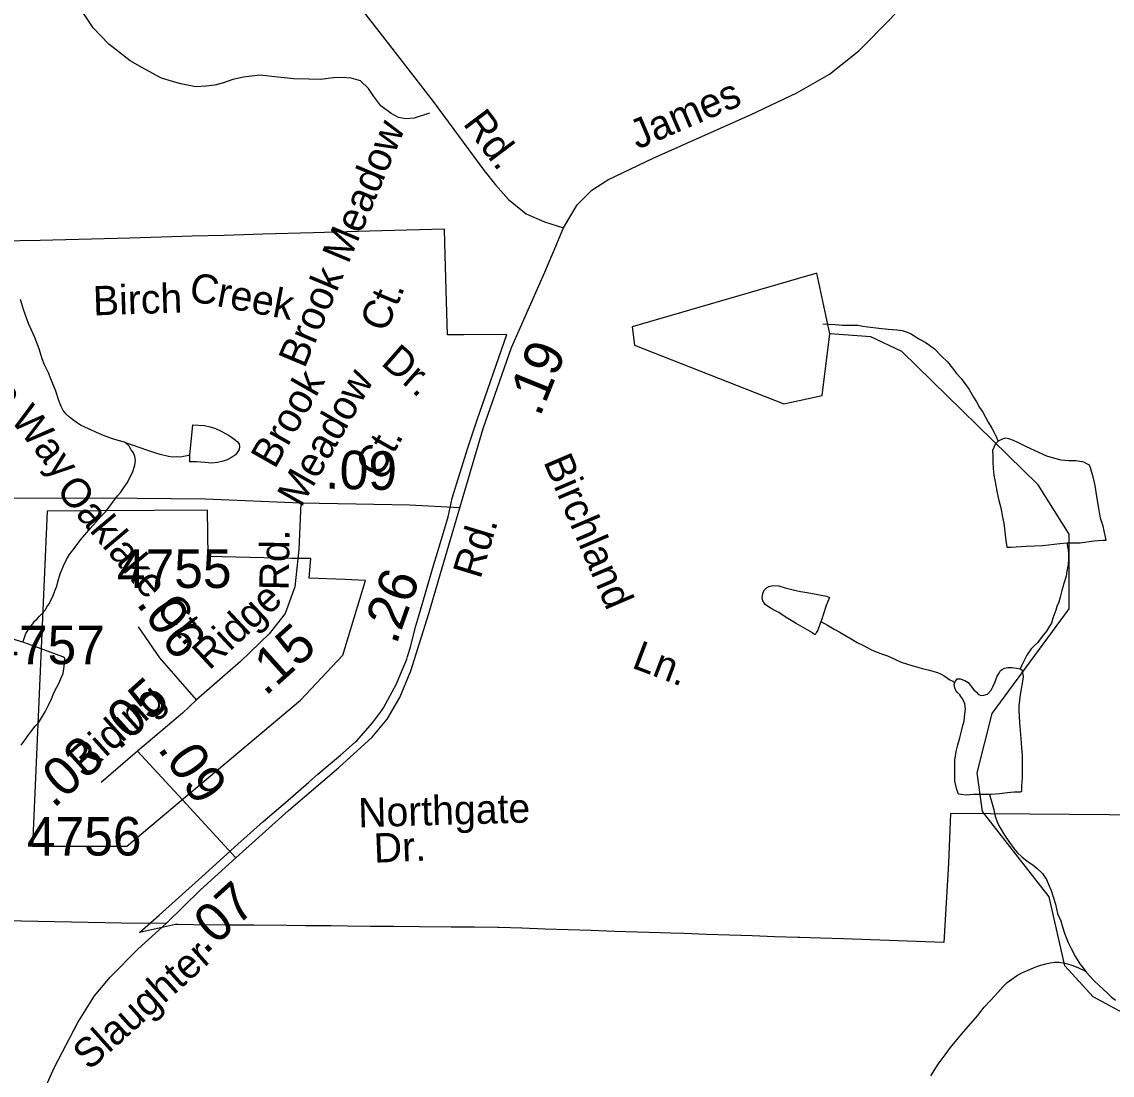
# Model space of a CAD drawing. Extents: x 2001466 to 2224147, y 644118 to 847247.
# Drawn here: x 2058752 to 2062288, y 676786 to 680203 of the extents above; entities that cross this region are included whole.
import ezdxf

# ---------------------------------------------------------------- set-up
doc = ezdxf.new("R2010")
doc.units = 0
for name, color, linetype in [('Exist Boundary Political City Limit New', 7, 'Continuous'), ('Exist Hydrographic Creek Single Shore', 7, 'Continuous'), ('Exist Hydrographic Misc Water Feature', 7, 'Continuous'), ('Exist Road Non-System Type 51', 7, 'Continuous'), ('Exist Road Non-System Type 51 Label', 7, 'Continuous'), ('Exist Road Secondary Mileage Hundredths English Label', 7, 'Continuous'), ('Exist Road Secondary Type 51 Attributed', 7, 'Continuous'), ('Exist Road Secondary Type 51 Label', 7, 'Continuous'), ('Exist Road Secondary Type 51 Number Label', 7, 'Continuous'), ('Map Preparation Boundary City Limit Buffer Line', 7, 'Continuous')]:
    doc.layers.add(name, color=color, linetype=linetype)

msp = doc.modelspace()

# ---------------------------------------------------------------- linework, layer by layer
at = {"layer": 'Exist Boundary Political City Limit New'}
for points in [[(2059452.1, 677535.1), (2059533.4, 677608.2), (2059607, 677670.7), (2059682.5, 677736.1), (2059712.1, 677762.4), (2059759.4, 677802.6), (2059785, 677824.4), (2059832.6, 677866.1), (2059838.1, 677870.9), (2059889.2, 677928.5), (2059918.5, 677968.4), (2059925, 677977.2), (2059966.5, 678055), (2059979.6, 678086.7), (2060000, 678135.8), (2060003, 678144), (2060012.4, 678174.8), (2060013.6, 678179.8), (2060029.4, 678243.4), (2060039.1, 678276.2), (2060067.4, 678372.6), (2060088.9, 678446.4), (2060096.4, 678471.2), (2060134.5, 678597.1), (2060147.6, 678657.4), (2060198.5, 678821.2), (2060227.9, 678911.3), (2060324.4, 679189.1), (2060185.2, 679187.9), (2060132.6, 679187.4), (2060130.5, 679258.9), (2060124.9, 679446), (2060122.4, 679530.6), (2060000, 679527), (2059879.4, 679523.6), (2059696.1, 679518.4), (2059533.2, 679513.8), (2059408, 679510.2), (2059303.9, 679507.2), (2059205, 679504.4), (2059102.2, 679501.5), (2058811.8, 679493.2), (2058678, 679491.1)], [(2059683.2, 678398.4), (2059688.8, 678462.5), (2059626.6, 678461.9), (2059356.6, 678468.5), (2059353.5, 678619.2), (2058834, 678615.1), (2058786.9, 677529.5), (2059092.8, 677529.5), (2059655.1, 678002.2), (2059792.6, 678148.9), (2059865.9, 678391.2), (2059798.8, 678393.9), (2059683.2, 678398.4)], [(2062406.8, 677630), (2061762.8, 677635.2), (2061756.4, 677473.4), (2061741.4, 677216.8), (2061504.9, 677225.1), (2061415.9, 677228.1), (2061341.9, 677230.6), (2061274.2, 677232.8), (2061268, 677233), (2061194, 677235.4), (2061120, 677237.9), (2061046.1, 677240.3), (2060972.1, 677242.8), (2060898.1, 677245.2), (2060854.9, 677246.6), (2060823.2, 677247.7), (2060748.2, 677250.2), (2060673.2, 677252.6), (2060598.4, 677255.1), (2060523.4, 677257.6), (2060448.4, 677260.1), (2060373.5, 677262.6), (2060298.5, 677265.1), (2060294.2, 677265.1), (2060219.5, 677265.8), (2060156.2, 677266.4), (2060144.5, 677266.5), (2060041.6, 677267.5), (2059957.6, 677268.2), (2059882.8, 677268.9), (2059807.8, 677269.7), (2059754.8, 677270.1), (2059671.8, 677270.9), (2059610.9, 677271.5), (2059503.9, 677272.3), (2059421.9, 677273.1), (2059309.8, 677274.1), (2059258.1, 677274.6), (2059250.2, 677274.9), (2059133.2, 677249.2)], [(2059133.2, 677249.2), (2059197.4, 677304.9), (2059335.2, 677429.4), (2059405.9, 677493.2), (2059452.1, 677535.1)]]:
    msp.add_lwpolyline(points, dxfattribs=at)
at = {"layer": 'Exist Hydrographic Creek Single Shore'}
msp.add_lwpolyline([(2062432.6, 676929.3), (2062225.6, 677040.6), (2062133.5, 677140.8), (2062083.5, 677365), (2061866.6, 677641.7), (2061849.6, 677766.6), (2061898.6, 677959.2), (2062148.5, 678298.7), (2062147.5, 678541.4), (2062047.6, 678701), (2061605.5, 679133.2), (2061504.7, 679181.1), (2061371.6, 679190.4)], dxfattribs=at)
at = {"layer": 'Exist Hydrographic Misc Water Feature'}
for points in [[(2061371.6, 679190.4), (2061329.5, 679388.1), (2060730.6, 679213.3), (2060738.6, 679154.1), (2061222.7, 678963.8), (2061347.6, 678990.8), (2061371.6, 679190.4)], [(2059088.1, 678836.8), (2059084.4, 678839.1), (2059064.5, 678844.9), (2059042.2, 678851.1), (2059016.6, 678860.7), (2058994.4, 678870.9), (2058976.2, 678879), (2058957.9, 678886.6), (2058942.3, 678894.6), (2058928.2, 678904.5), (2058916.1, 678912.8), (2058906.2, 678920.4), (2058896, 678930.5), (2058886.1, 678942.5), (2058880, 678954.8), (2058871.8, 678974.7), (2058861.9, 679004.5), (2058846.2, 679044.3), (2058838, 679064.6), (2058825.6, 679090.4), (2058818.1, 679110.2), (2058807.6, 679142.6), (2058793.7, 679178.4), (2058783.6, 679202.2), (2058773.8, 679224.4), (2058757.6, 679270.2), (2058747.5, 679302.2)], [(2061349.2, 679222.9), (2061389.2, 679221.3), (2061413.2, 679219.3), (2061429.4, 679219.3), (2061447.2, 679219.4), (2061463, 679219.4), (2061478.8, 679215.4), (2061495, 679213.4), (2061531.1, 679209.5), (2061560.8, 679205.4), (2061589.1, 679203.6), (2061607, 679201.7), (2061619.1, 679197.4), (2061633, 679191.7)], [(2061633, 679191.7), (2061663.2, 679173.7), (2061681, 679163.7), (2061695.1, 679153.8), (2061710.9, 679141.7), (2061733.3, 679119.7), (2061753.4, 679100), (2061769.2, 679079.8), (2061783.1, 679061.8), (2061797.5, 679045.9), (2061809.2, 679029.9), (2061823.3, 679009.9), (2061837.7, 678985.8), (2061847.7, 678970.1), (2061857.5, 678952), (2061867.6, 678936.3), (2061885.6, 678904.3), (2061897.5, 678884.3), (2061909.6, 678862.1), (2061917.8, 678842.2)], [(2059296.2, 678797.2), (2059306.3, 678895.5), (2059344.2, 678893.4), (2059362.3, 678889.4), (2059379.9, 678883.5), (2059398.2, 678875.4), (2059422.1, 678861.6), (2059432.2, 678855.7), (2059440.2, 678849.6), (2059449.8, 678841.6), (2059456.2, 678833.8), (2059457.8, 678825.8), (2059456.2, 678815.5), (2059450.2, 678805.9), (2059444.3, 678797.9), (2059432.2, 678789.6), (2059418.2, 678781.6), (2059404.3, 678777.6), (2059386.3, 678773.4), (2059368, 678771.7), (2059346.3, 678773.4), (2059318.2, 678775.6), (2059296.4, 678775.2), (2059296.2, 678797.2)], [(2062140.5, 678512.8), (2062184.2, 678512.7), (2062228.1, 678519), (2062257.8, 678521), (2062268.1, 678521), (2062257.8, 678566.8), (2062249.8, 678592.8), (2062243.7, 678624.9), (2062238.1, 678662.7), (2062231.8, 678698.9), (2062225.8, 678726.6), (2062221.7, 678740.6), (2062217.6, 678756.6), (2062213.9, 678764.9), (2062205.5, 678768.6), (2062195.5, 678774.6), (2062169.4, 678778.6), (2062145.6, 678778.5), (2062121.7, 678780.5), (2062101.8, 678786.4), (2062075.5, 678794.4), (2062035.7, 678812.6), (2062009.5, 678824.3), (2061981.8, 678838.3), (2061967.9, 678844.4), (2061951.9, 678850.1), (2061941.6, 678852.5), (2061933.6, 678850.4), (2061917.8, 678842.2)], [(2058755.5, 678190.4), (2058759.2, 678202.4), (2058765.4, 678218.6), (2058775.2, 678234.5), (2058781.4, 678242.5), (2058787.3, 678250.5), (2058793.2, 678258.5), (2058801.5, 678266.6), (2058809.2, 678274.8), (2058817.2, 678282.5), (2058827.5, 678294.8), (2058835.3, 678308.5), (2058841.2, 678316.6), (2058845.1, 678324.5), (2058852.9, 678338.7), (2058859.1, 678356.9), (2058865, 678372.6), (2058869.1, 678386.6), (2058876.7, 678412.6), (2058887.2, 678438.6), (2058896.8, 678458.6), (2058906.6, 678474.6), (2058924.7, 678498.6), (2058942.7, 678522.6), (2058956.5, 678538.8), (2058974.5, 678560.8), (2058992.8, 678580.8), (2059006.5, 678596.9), (2059024.3, 678614.9), (2059036.4, 678630.9), (2059046.9, 678644.8), (2059062.5, 678665.1), (2059072.5, 678677), (2059080.5, 678689.1), (2059094.5, 678708.9), (2059104.3, 678729), (2059110.5, 678741), (2059118.3, 678764.9), (2059120.1, 678780.9), (2059118.3, 678792.9), (2059114.4, 678804.9), (2059106.2, 678815), (2059100.2, 678826.9), (2059088.1, 678836.8)], [(2059296.2, 678797.2), (2059288.2, 678795.1), (2059276.1, 678793.3), (2059266.3, 678791.2), (2059254, 678791.4), (2059242.1, 678791.2), (2059228, 678793.3), (2059200.1, 678799.2), (2059186.3, 678803.3), (2059176.3, 678807.2), (2059154.3, 678815), (2059142.2, 678819.3), (2059108, 678831), (2059088.1, 678836.8)], [(2061917.8, 678842.2), (2061907.6, 678832), (2061903.9, 678822.1), (2061899.6, 678812.2), (2061900, 678794.3), (2061900, 678776), (2061901.8, 678754.2), (2061903.7, 678732.4), (2061907.8, 678710.3), (2061913.7, 678680.2), (2061919.7, 678650.1), (2061926, 678626.4), (2061932, 678596.3), (2061935.9, 678576.3), (2061938.1, 678558.5), (2061940.2, 678538.3), (2061942.2, 678520.2), (2061944.3, 678506.5), (2061946.3, 678498.4), (2061960.3, 678498.3), (2062008.3, 678502.4), (2062062.2, 678504.4), (2062118, 678510.6), (2062140.5, 678512.8)], [(2062140.5, 678512.8), (2062144.4, 678490.7), (2062146.3, 678478.7), (2062146.3, 678458.8), (2062144.4, 678442.9), (2062140.3, 678420.8), (2062138.1, 678404.9), (2062130.3, 678380.5), (2062124.5, 678358.7), (2062118.4, 678336.9), (2062114.9, 678320.8), (2062108.5, 678306.8), (2062104.4, 678294.8), (2062094.6, 678268.7), (2062090.7, 678252.7), (2062084.7, 678242.6), (2062074.9, 678226.7), (2062064.9, 678214.4), (2062056.9, 678204.7), (2062044.8, 678188.6), (2062034.9, 678178.4), (2062024.9, 678168.6), (2062016.7, 678158.4), (2062010.9, 678148.8), (2061999.2, 678124.6), (2061994.9, 678116.3), (2061989, 678104.6)], [(2061342.9, 678257.3), (2061332.8, 678229.2), (2061328.7, 678223.4), (2061324.8, 678215), (2061308.6, 678225.2), (2061262.9, 678251.2), (2061230.9, 678271.1), (2061206.7, 678286.9), (2061186.8, 678296.8), (2061172.9, 678305), (2061162.6, 678313.1), (2061154.4, 678324.9), (2061152.8, 678334.8), (2061154.6, 678348.7), (2061158.9, 678359), (2061166.5, 678366.8), (2061172.7, 678370.7), (2061188.7, 678374.8), (2061206.7, 678372.9), (2061226.6, 678367), (2061248.5, 678361.3), (2061276.8, 678354.9), (2061298.8, 678351.3), (2061332.6, 678345.3), (2061360.9, 678339.4), (2061370.8, 678335.4), (2061360.5, 678309.4), (2061352.7, 678285.4), (2061344.9, 678261.5), (2061342.9, 678257.3)], [(2061342.9, 678257.3), (2061364.8, 678245.5), (2061386.5, 678233.3), (2061404.8, 678223.2), (2061420.6, 678213.5), (2061440.7, 678201.5), (2061461, 678189.6), (2061480.9, 678179.6), (2061503.2, 678167.7), (2061517, 678161.6), (2061543, 678151.6), (2061559, 678145.9), (2061582.8, 678135.8), (2061602.9, 678125.8), (2061620.9, 678119.9), (2061640.8, 678114), (2061657.2, 678109.9), (2061671, 678105.8), (2061694.9, 678100.1), (2061709.3, 678095.9), (2061721, 678092.1), (2061730.8, 678088.2), (2061742.9, 678081.9), (2061753.2, 678073.9), (2061761.2, 678068.2), (2061771, 678064.2), (2061777.2, 678060.1)], [(2058755.5, 678190.4), (2058659.4, 678220.4)], [(2058750.2, 677856.7), (2058761.7, 677872.7), (2058774.2, 677890.8), (2058784, 677904.6), (2058795.7, 677918.7), (2058806, 677928.5), (2058815.8, 677944.8), (2058828.1, 677964.5), (2058838.2, 677986.5), (2058847.8, 678006.5), (2058855.8, 678026.8), (2058865.6, 678044.8), (2058873.4, 678058.6), (2058879.6, 678074.7), (2058885.7, 678088.8), (2058887.6, 678104.7), (2058891.5, 678128.9), (2058891.5, 678138.6), (2058885.3, 678142.8), (2058773.8, 678184.4), (2058755.5, 678190.4)], [(2061777.2, 678060.1), (2061779.2, 678064.2), (2061785.2, 678072.2), (2061795, 678072), (2061809.2, 678066.2), (2061821, 678060.3), (2061831.1, 678046.2), (2061839.1, 678036.1), (2061847.1, 678028.4), (2061852.8, 678022.2), (2061861.2, 678018.1), (2061870.9, 678018.3), (2061883.2, 678022.1), (2061894.9, 678034.5), (2061901, 678046.1), (2061907.4, 678060.2), (2061915, 678080.6), (2061920.7, 678090.2), (2061925.2, 678098.5), (2061931, 678102.5), (2061938.7, 678106.6), (2061948.8, 678108.3), (2061962.9, 678108.6), (2061977.1, 678106.4), (2061989, 678104.6)], [(2061989, 678104.6), (2061994.7, 678100.5), (2061996.8, 678092.5), (2061999.2, 678078.3), (2061996.8, 678064.5), (2061993.1, 678044.4), (2061989.2, 678020.7), (2061986.9, 678002.7), (2061985.1, 677984.4), (2061985.1, 677966.5), (2061985.5, 677950.6), (2061987.3, 677930.5), (2061991.2, 677878.4), (2061993.5, 677848.4), (2061995.1, 677822.6), (2061995.5, 677796.6), (2061995.3, 677772.7), (2061995.5, 677750.3), (2061993.3, 677724.7), (2061993.7, 677714.5), (2061993.7, 677706.4), (2061989.6, 677704.6), (2061969.5, 677704.4), (2061948, 677702.4), (2061921.7, 677698.3), (2061895.5, 677696.6), (2061889.5, 677696.3)], [(2061889.5, 677696.3), (2061869.6, 677696.4), (2061837.7, 677696.4), (2061813.7, 677694.4), (2061797.7, 677696.4), (2061789.5, 677698.1), (2061783.9, 677712.3), (2061777.8, 677739.9), (2061777.6, 677754.2), (2061777.6, 677782.2), (2061777.8, 677808.1), (2061781.5, 677836.3), (2061787.4, 677858.2), (2061793.6, 677879.9), (2061799.3, 677902.2), (2061803.6, 677920.2), (2061807.3, 677934.2), (2061809.2, 677958.3), (2061811.4, 677974.2), (2061809.4, 677990.3), (2061803, 678006.3), (2061797.1, 678014), (2061793.2, 678020.3), (2061786.8, 678026.1), (2061780.9, 678034), (2061777.2, 678042.2), (2061774.9, 678053.9), (2061777.2, 678060.1)], [(2061889.5, 677696.3), (2061897.5, 677670.3), (2061903.9, 677646.6), (2061907.8, 677626.6), (2061916, 677604.7), (2061923.8, 677588.5), (2061938.1, 677564.4), (2061951.9, 677544.5), (2061969.9, 677520.6), (2061979.8, 677508.6), (2061994.1, 677494.6), (2062012.2, 677480.5), (2062030.2, 677468.5), (2062044.4, 677456.6), (2062062, 677440.6), (2062074.1, 677420.9), (2062082.1, 677402.6), (2062090.1, 677384.8), (2062096.2, 677364.8), (2062104, 677340.9), (2062110.6, 677310.7), (2062120.6, 677286.9), (2062126.6, 677266.9), (2062132.5, 677246.9), (2062138.3, 677233.1), (2062144.6, 677216.7), (2062154.5, 677197), (2062160.6, 677185.1), (2062166.6, 677172.8), (2062174.4, 677161.1), (2062182.6, 677146.9), (2062192.6, 677135.2), (2062200.8, 677123)], [(2061699.2, 676784.1), (2061723, 676822.3), (2061745.4, 676852.2), (2061763, 676876.3), (2061783.3, 676900.4), (2061805.1, 676926.3), (2061829.3, 676954.2), (2061851, 676978.5), (2061872.7, 677006.5), (2061893, 677028.5), (2061916.8, 677054.5), (2061932.6, 677072.8), (2061947, 677086.5), (2061976.9, 677108.7), (2061994.7, 677118.6), (2062014.8, 677126.9), (2062032.7, 677134.7), (2062048.7, 677140.8), (2062072.6, 677146.9), (2062086.4, 677150.9), (2062100.7, 677152.8), (2062114.9, 677153.1), (2062128.4, 677151), (2062142.8, 677146.8), (2062156.9, 677143), (2062176.4, 677135.2), (2062200.8, 677123)], [(2062200.8, 677123), (2062204.7, 677119.1), (2062214.7, 677107.1), (2062228.5, 677093.3), (2062244.9, 677077), (2062258.6, 677065.2), (2062273, 677051.2), (2062285.1, 677039.3), (2062298.6, 677029.5)]]:
    msp.add_lwpolyline(points, dxfattribs=at)
at = {"layer": 'Exist Road Non-System Type 51'}
msp.add_lwpolyline([(2060074, 679906.9), (2060023.6, 679889.9), (2059997.6, 679888.4), (2059973.7, 679892.9), (2059950, 679905.4), (2059916.5, 679930.1), (2059893.1, 679960.5), (2059875.6, 679986.9), (2059850.1, 680011.4), (2059820.3, 680020), (2059790.3, 680022.6), (2059762.3, 680021.2), (2059720.2, 680016.1), (2059682.2, 680016.8), (2059634.2, 680017.8), (2059582.3, 680022.9), (2059524.5, 680030), (2059496.4, 680026.6), (2059470.3, 680023.1), (2059436.2, 680015.8), (2059406, 680004.4), (2059377.8, 679997), (2059349.7, 679993.6), (2059315.7, 679992.3), (2059267.9, 680001.2), (2059240.1, 680009.8), (2059204.3, 680020.5), (2059150.9, 680049.6), (2059103.4, 680076.6), (2059034.5, 680130), (2058983.6, 680183), (2058944.8, 680241.8)], dxfattribs=at)
at = {"layer": 'Exist Road Secondary Type 51 Attributed'}
for points in [[(2060508, 679534.3), (2060552.2, 679608.9), (2060600.6, 679656.5), (2060652.2, 679690.1), (2060798.9, 679760.6), (2061116.9, 679901.7), (2061264.5, 679972.2), (2061371, 680032.9), (2061466.1, 680108.3), (2061569.4, 680213.3), (2061756.2, 680423.2), (2061943.1, 680639.7), (2062112, 680856.2), (2062225, 681020.9), (2062307, 681148)], [(2059729.5, 680403.8), (2059936.2, 680137), (2060085.3, 679944.7), (2060249.8, 679721.3), (2060287.5, 679673.7), (2060330.1, 679627), (2060387.5, 679580.2), (2060446.5, 679554), (2060508, 679534.3)], [(2060172.5, 678626.2), (2060247.8, 678883.6), (2060339.3, 679146.1), (2060447.3, 679390.8), (2060483.4, 679475.3), (2060508, 679534.3)], [(2059656.9, 678641.6), (2059346.8, 678654.3), (2059015.5, 678657.4), (2058708.6, 678656.3), (2058269.9, 678661.8), (2057803.6, 678666.1), (2057279.8, 678673.6)], [(2059656.9, 678641.6), (2059650.6, 678491.6), (2059637.2, 678370.4), (2059605.6, 678283.6), (2059553.5, 678217.3), (2059461.2, 678127.7), (2059318.4, 678003.7)], [(2060172.5, 678626.2), (2060009.5, 678635.1), (2059836.3, 678638.5), (2059656.9, 678641.6)], [(2059446, 677490.7), (2059616.7, 677644.3), (2059780.1, 677783.8), (2059887.6, 677882.7), (2059936.7, 677941.1), (2059977.2, 678011.2), (2060012.9, 678097.2), (2060071.2, 678284), (2060115.4, 678432.1), (2060172.5, 678626.2)], [(2059318.4, 678003.7), (2059199.3, 678139.5), (2059129.9, 678240.6)], [(2059318.4, 678003.7), (2059272.7, 677959.9), (2059127.5, 677836.7)], [(2059127.5, 677836.7), (2059009.2, 677735.7)], [(2059446, 677490.7), (2059285.3, 677666.2), (2059127.5, 677836.7)], [(2059220, 677278.1), (2059331.8, 677386.9), (2059446, 677490.7)], [(2059220, 677278.1), (2059075.4, 677279.4), (2058751.2, 677285.3), (2058346.4, 677295.9), (2057959, 677297.1), (2057536.3, 677289.9), (2057333.6, 677286.4)], [(2058183.1, 675136.2), (2058261.4, 675239.4), (2058354.7, 675369), (2058425.3, 675480.2), (2058576.8, 675760.7), (2058663.9, 675907.3), (2058689.7, 675958.9), (2058720.7, 676048), (2058739.2, 676149.4), (2058752.7, 676278.4), (2058763.1, 676404.4), (2058789.5, 676631.1), (2058814.7, 676715.3), (2058856.8, 676810.5), (2058933.5, 676957.4), (2058987.6, 677043.4), (2059037.9, 677104.2), (2059127.9, 677195.2), (2059220, 677278.1)]]:
    msp.add_lwpolyline(points, dxfattribs=at)
at = {"layer": 'Map Preparation Boundary City Limit Buffer Line'}
for points in [[(2059452.1, 677535.1), (2059533.4, 677608.2), (2059607, 677670.7), (2059682.5, 677736.1), (2059712.1, 677762.4), (2059759.4, 677802.6), (2059785, 677824.4), (2059832.6, 677866.1), (2059838.1, 677870.9), (2059889.2, 677928.5), (2059918.5, 677968.4), (2059925, 677977.2), (2059966.5, 678055), (2059979.6, 678086.7), (2060000, 678135.8), (2060003, 678144), (2060012.4, 678174.8), (2060013.6, 678179.8), (2060029.4, 678243.4), (2060039.1, 678276.2), (2060067.4, 678372.6), (2060088.9, 678446.4), (2060096.4, 678471.2), (2060134.5, 678597.1), (2060147.6, 678657.4), (2060198.5, 678821.2), (2060227.9, 678911.3), (2060324.4, 679189.1), (2060185.2, 679187.9), (2060132.6, 679187.4), (2060130.5, 679258.9), (2060124.9, 679446), (2060122.4, 679530.6), (2060000, 679527), (2059879.4, 679523.6), (2059696.1, 679518.4), (2059533.2, 679513.8), (2059408, 679510.2), (2059303.9, 679507.2), (2059205, 679504.4), (2059102.2, 679501.5), (2058811.8, 679493.2), (2058678, 679491.1)], [(2059683.2, 678398.4), (2059688.8, 678462.5), (2059626.6, 678461.9), (2059356.6, 678468.5), (2059353.5, 678619.2), (2058834, 678615.1), (2058786.9, 677529.5), (2059092.8, 677529.5), (2059655.1, 678002.2), (2059792.6, 678148.9), (2059865.9, 678391.2), (2059798.8, 678393.9), (2059683.2, 678398.4)], [(2062406.8, 677630), (2061762.8, 677635.2), (2061756.4, 677473.4), (2061741.4, 677216.8), (2061504.9, 677225.1), (2061415.9, 677228.1), (2061341.9, 677230.6), (2061274.2, 677232.8), (2061268, 677233), (2061194, 677235.4), (2061120, 677237.9), (2061046.1, 677240.3), (2060972.1, 677242.8), (2060898.1, 677245.2), (2060854.9, 677246.6), (2060823.2, 677247.7), (2060748.2, 677250.2), (2060673.2, 677252.6), (2060598.4, 677255.1), (2060523.4, 677257.6), (2060448.4, 677260.1), (2060373.5, 677262.6), (2060298.5, 677265.1), (2060294.2, 677265.1), (2060219.5, 677265.8), (2060156.2, 677266.4), (2060144.5, 677266.5), (2060041.6, 677267.5), (2059957.6, 677268.2), (2059882.8, 677268.9), (2059807.8, 677269.7), (2059754.8, 677270.1), (2059671.8, 677270.9), (2059610.9, 677271.5), (2059503.9, 677272.3), (2059421.9, 677273.1), (2059309.8, 677274.1), (2059258.1, 677274.6), (2059250.2, 677274.9), (2059133.2, 677249.2)], [(2059133.2, 677249.2), (2059197.4, 677304.9), (2059335.2, 677429.4), (2059405.9, 677493.2), (2059452.1, 677535.1)]]:
    msp.add_lwpolyline(points, dxfattribs=at)

# ---------------------------------------------------------------- texts
at = {"layer": 'Exist Road Non-System Type 51 Label'}
for s, rotation, p in [('Brook Meadow ', 67.2749, (2059668.5, 679075.9)), ('Magnolia Ridge Way', 308.2428, (2058143.8, 679633.4)), ('Creek', 349.2955, (2059290.6, 679298.4)), ('Birch', 1.9102, (2058984, 679250.4)), ('Ct.', 67.2749, (2059932.6, 679192)), ('Dr.', 318.6796, (2059913.2, 679092.8)), ('Brook', 60.2865, (2059572.1, 678749.4)), ('Meadow', 60.2865, (2059657.5, 678624.1)), ('Ct.', 60.2865, (2059911.1, 678718.8)), ('Birchland', 293.1898, (2060442.1, 678776.2)), ('Ln.', 339.2199, (2060726.2, 678109)), ('Northgate', 1.628, (2059843.8, 677590)), ('Dr.', 2.3854, (2059895, 677475.2))]:
    msp.add_text(s, height=95, rotation=rotation, dxfattribs=at).set_placement(p)
at = {"layer": 'Exist Road Secondary Mileage Hundredths English Label'}
for s, rotation, p in [('.19', 67.9791, (2060431.5, 678918.5)), ('.09', 358.8366, (2059734.8, 678688.6)), ('.26', 70.4163, (2059966.1, 678179.9)), ('.06', 305.0153, (2059120.7, 678316.4)), ('.15', 41.9207, (2059541.7, 678013.1)), ('.05', 41.9207, (2059064.6, 677837.7)), ('.03', 41.9207, (2058854.6, 677649.1)), ('.09', 305.0153, (2059189.8, 677845.2)), ('.07', 41.9207, (2059346, 677175))]:
    msp.add_text(s, height=125, rotation=rotation, dxfattribs=at).set_placement(p)
at = {"layer": 'Exist Road Secondary Type 51 Label'}
for s, rotation, p in [('James', 23.2066, (2060748.2, 679788)), ('Rd.', 306.972, (2060179.9, 679872.6)), ('Oaklake Ct.', 310.0667, (2058860, 678681.6)), ('Rd.', 73.0362, (2060238.7, 678392.7)), ('Rd.', 88.8769, (2059616.7, 678358.1)), ('Ridge', 42.9611, (2059359.7, 678097.1)), ('Riding', 41.9934, (2058955, 677753.8)), ('Slaughter', 41.9181, (2058970.5, 676799.1))]:
    msp.add_text(s, height=95, rotation=rotation, dxfattribs=at).set_placement(p)
at = {"layer": 'Exist Road Secondary Type 51 Number Label'}
for s, p in [('4755', (2059060.1, 678366.4)), ('4757', (2058649.5, 678119.2)), ('4756', (2058768.2, 677498.6))]:
    msp.add_text(s, height=125, dxfattribs=at).set_placement(p)

doc.saveas('drawing.dxf')
